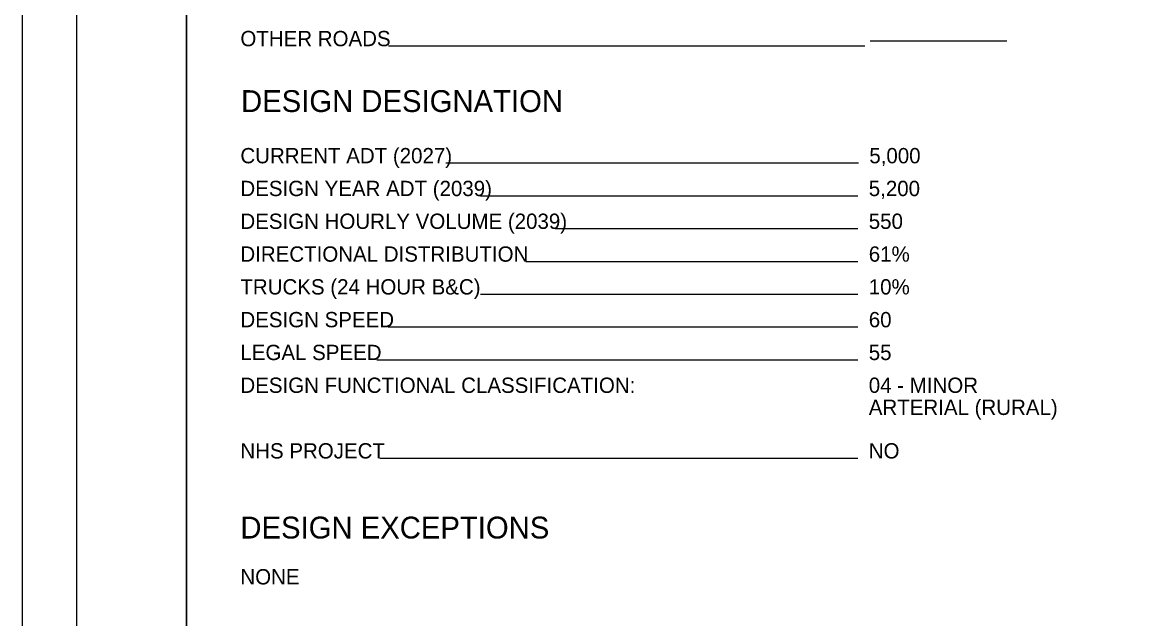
# Model space of a CAD drawing. Extents: x 0 to 34, y 0 to 22.
# Drawn here: x 0 to 10.15, y 5.64 to 11.1 of the extents above; entities that cross this region are included whole.
import ezdxf

# ---------------------------------------------------------------- set-up
doc = ezdxf.new("R2010")
doc.units = 0
for name, color, linetype in [('SH_Border', 7, 'Continuous'), ('SH_Cut_Line', 7, 'Continuous'), ('SH_Data', 7, 'Continuous'), ('SH_Text', 7, 'Continuous')]:
    doc.layers.add(name, color=color, linetype=linetype)

msp = doc.modelspace()

# ---------------------------------------------------------------- linework, layer by layer
at = {"layer": 'SH_Border'}
for points in [[(0.5, 21.5), (1.5, 21.5), (1.5, 0.5), (0.5, 0.5)], [(1.5, 21.5), (33.5, 21.5), (33.5, 0.5), (1.5, 0.5)]]:
    msp.add_lwpolyline(points, close=True, dxfattribs=at)
at = {"layer": 'SH_Cut_Line'}
msp.add_lwpolyline([(0, 0), (34, 0), (34, 22), (0, 22)], close=True, dxfattribs=at)
at = {"layer": 'SH_Data'}
for p, q in [((7.7, 10.877), (3.347, 10.877)), ((9, 10.922), (7.75, 10.922)), ((7.642, 9.806), (3.871, 9.806)), ((7.637, 9.506), (4.189, 9.506)), ((7.637, 9.206), (4.872, 9.206)), ((7.637, 8.906), (4.604, 8.906)), ((7.637, 8.606), (4.189, 8.606)), ((7.637, 8.306), (3.346, 8.306)), ((7.637, 8.006), (3.242, 8.006)), ((7.637, 7.106), (3.267, 7.106))]:
    msp.add_line(p, q, dxfattribs=at)

# ---------------------------------------------------------------- texts
msp.add_text('DESIGN DESIGNATION', height=0.2, dxfattribs=at).set_placement((2, 10.275))
at = {"layer": 'SH_Text'}
for s, height, p in [('OTHER ROADS', 0.14, (1.994, 10.877)), ('CURRENT ADT (2027)', 0.14, (1.994, 9.806)), ('5,000', 0.14, (7.742, 9.806)), ('DESIGN YEAR ADT (2039)', 0.14, (1.994, 9.506)), ('5,200', 0.14, (7.737, 9.506)), ('DESIGN HOURLY VOLUME (2039)', 0.14, (1.994, 9.206)), ('550', 0.14, (7.737, 9.206)), ('DIRECTIONAL DISTRIBUTION', 0.14, (1.994, 8.906)), ('61%', 0.14, (7.737, 8.906)), ('TRUCKS (24 HOUR B&C)', 0.14, (1.994, 8.606)), ('10%', 0.14, (7.737, 8.606)), ('DESIGN SPEED', 0.14, (1.994, 8.306)), ('60', 0.14, (7.737, 8.306)), ('LEGAL SPEED', 0.14, (1.994, 8.006)), ('55', 0.14, (7.737, 8.006)), ('DESIGN FUNCTIONAL CLASSIFICATION:', 0.14, (1.994, 7.706)), ('04 - MINOR ', 0.14, (7.737, 7.706)), ('ARTERIAL (RURAL)', 0.14, (7.737, 7.504)), ('NHS PROJECT', 0.14, (1.994, 7.106)), ('NO', 0.14, (7.737, 7.106)), ('DESIGN EXCEPTIONS', 0.2, (1.994, 6.374)), ('NONE', 0.14, (1.994, 5.954))]:
    msp.add_text(s, height=height, dxfattribs=at).set_placement(p)

doc.saveas('drawing.dxf')
